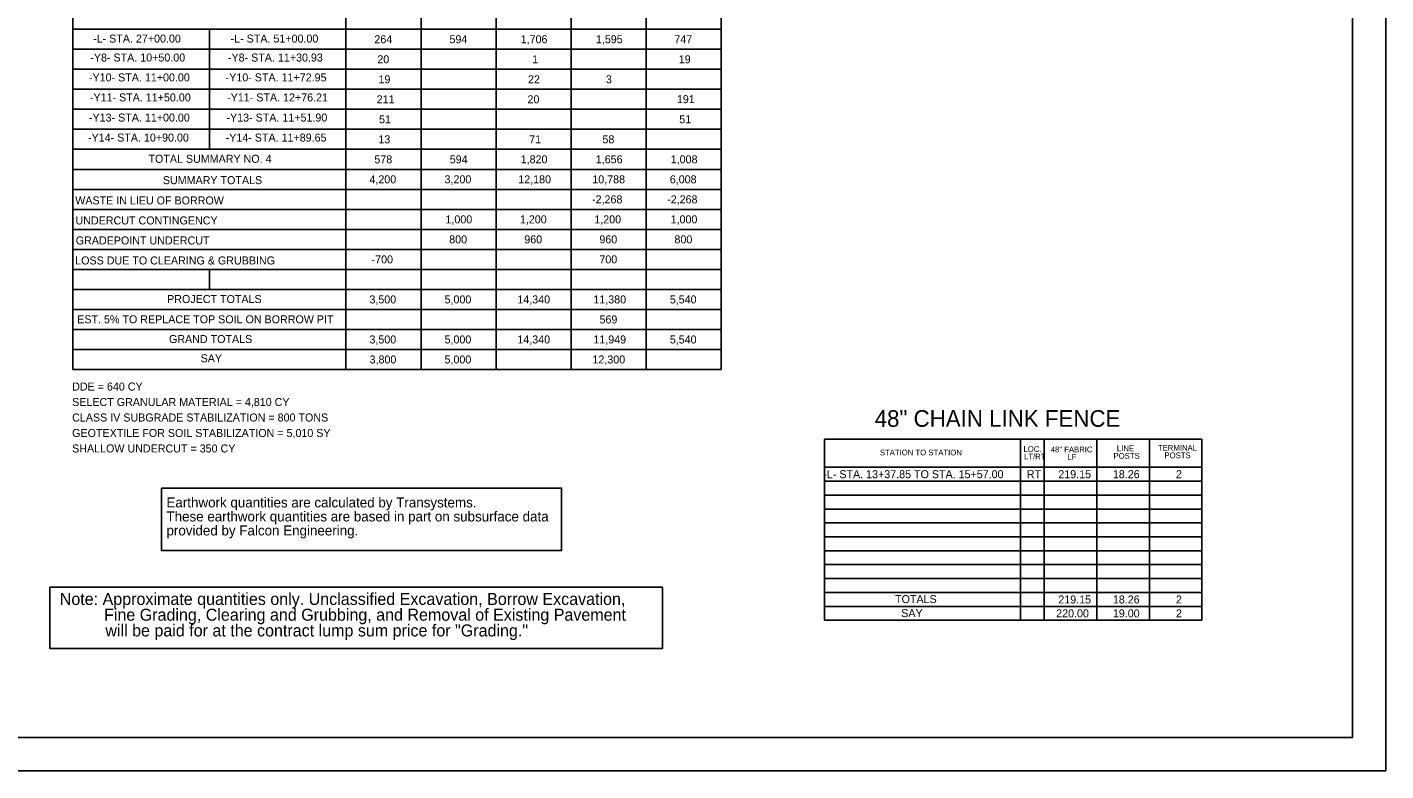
# Model space of a CAD drawing. Extents: x 573680 to 575380, y -53324 to -52224.
# Drawn here: x 574361 to 575380, y -53324 to -52767 of the extents above; entities that cross this region are included whole.
import ezdxf

# ---------------------------------------------------------------- set-up
doc = ezdxf.new("R2010")
doc.units = 0
for name, color, linetype in [('Old_Level_1', 7, 'Continuous'), ('Prop Dimension Text', 7, 'Continuous'), ('Prop Grid Mask', 7, 'Continuous'), ('Prop XSC Text', 7, 'Continuous'), ('Sheet Plan And Profile CELL', 7, 'Continuous'), ('Sheet Plot Border Outside CELL', 7, 'Continuous'), ('Sheet Summary Combination CELL', 7, 'Continuous'), ('Sheet Summary Combination Grid CELL', 7, 'Continuous'), ('Sheet Summary Earthwork CELL', 7, 'Continuous')]:
    doc.layers.add(name, color=color, linetype=linetype)

msp = doc.modelspace()

# ---------------------------------------------------------------- linework, layer by layer
at = {"layer": 'Prop Grid Mask'}
msp.add_lwpolyline([(574378.2, -53186.6), (574837.5, -53186.6), (574837.5, -53232.7), (574378.2, -53232.7)], close=True, dxfattribs=at)
at = {"layer": 'Sheet Plan And Profile CELL'}
msp.add_lwpolyline([(575354.9, -52249.3), (573854.9, -52249.3), (573854.9, -53299.3), (575354.9, -53299.3)], close=True, dxfattribs=at)
at = {"layer": 'Sheet Plot Border Outside CELL'}
msp.add_lwpolyline([(573679.9, -53324.3), (575379.9, -53324.3), (575379.9, -52224.3), (573679.9, -52224.3)], close=True, dxfattribs=at)
at = {"layer": 'Sheet Summary Combination CELL'}
for p, q in [((575084.8, -53075.9), (575084.8, -53075.9)), ((575090.1, -53076), (575090.1, -53076)), ((575097.7, -53075.8), (575097.7, -53075.8)), ((575102.4, -53075.9), (575102.4, -53075.9))]:
    msp.add_line(p, q, dxfattribs=at)
at = {"layer": 'Sheet Summary Combination Grid CELL'}
for p, q in [((574395.4, -52348.5), (574395.4, -53023.5)), ((574600.2, -52348.5), (574600.2, -53023.5)), ((574656.5, -52348.5), (574656.5, -53023.5)), ((574712.8, -52348.5), (574712.8, -53023.5)), ((574769.1, -52348.5), (574769.1, -53023.5)), ((574825.3, -52348.5), (574825.3, -53023.5)), ((574881.6, -52348.5), (574881.6, -53023.5)), ((574395.4, -52768.5), (574881.6, -52768.5)), ((574497.9, -52768.5), (574497.9, -52858.5)), ((574395.4, -52783.5), (574881.6, -52783.5)), ((574395.4, -52798.4), (574881.6, -52798.4)), ((574395.4, -52813.4), (574881.6, -52813.4)), ((574395.4, -52828.5), (574881.6, -52828.5)), ((574395.4, -52843.5), (574881.6, -52843.5)), ((574395.4, -52858.5), (574881.6, -52858.5)), ((574395.4, -52873.5), (574881.6, -52873.5)), ((574395.4, -52888.5), (574881.6, -52888.5)), ((574395.4, -52903.5), (574881.6, -52903.5)), ((574395.4, -52903.5), (574881.6, -52903.5)), ((574395.4, -52918.5), (574881.6, -52918.5)), ((574395.4, -52918.5), (574881.6, -52918.5)), ((574395.4, -52933.5), (574881.6, -52933.5)), ((574395.4, -52933.5), (574881.6, -52933.5)), ((574395.4, -52948.5), (574881.6, -52948.5)), ((574395.4, -52948.5), (574881.6, -52948.5)), ((574497.9, -52948.5), (574497.9, -52963.5)), ((574395.4, -52963.5), (574881.6, -52963.5)), ((574395.4, -52963.5), (574881.6, -52963.5)), ((574395.4, -52978.5), (574881.6, -52978.5)), ((574395.4, -52993.5), (574881.6, -52993.5)), ((574395.4, -53008.5), (574881.6, -53008.5)), ((574395.4, -53023.5), (574881.6, -53023.5)), ((574959, -53075.8), (575242, -53075.8)), ((574959, -53075.8), (574959, -53211.5)), ((575106, -53075.8), (575106, -53211.5)), ((575123.8, -53075.8), (575123.8, -53211.5)), ((575163.2, -53075.8), (575163.2, -53211.5)), ((575202.6, -53075.8), (575202.6, -53211.5)), ((575242, -53075.8), (575242, -53211.5)), ((574959, -53096.8), (575242, -53096.8)), ((574959, -53107.3), (575242, -53107.3)), ((574959, -53117.7), (575242, -53117.7)), ((574959, -53128.1), (575242, -53128.1)), ((574959, -53138.5), (575242, -53138.5)), ((574959, -53148.9), (575242, -53148.9)), ((574959, -53159.4), (575242, -53159.4)), ((574959, -53169.8), (575242, -53169.8)), ((574959, -53180.2), (575242, -53180.2)), ((574959, -53190.6), (575242, -53190.6)), ((574959, -53201.1), (575242, -53201.1)), ((574959, -53211.5), (575242, -53211.5))]:
    msp.add_line(p, q, dxfattribs=at)
at = {"layer": 'Sheet Summary Earthwork CELL'}
msp.add_lwpolyline([(574461.9, -53112.4), (574761.9, -53112.4), (574761.9, -53159.2), (574461.9, -53159.2)], close=True, dxfattribs=at)

# ---------------------------------------------------------------- texts
at = {"layer": 'Old_Level_1'}
for s, p in [('DDE = 640 CY', (574394.9, -53039.3)), ('SELECT GRANULAR MATERIAL = 4,810 CY', (574394.9, -53050.9)), ('CLASS IV SUBGRADE STABILIZATION = 800 TONS', (574394.9, -53062.5)), ('GEOTEXTILE FOR SOIL STABILIZATION = 5,010 SY', (574394.9, -53074.1)), ('SHALLOW UNDERCUT = 350 CY', (574394.9, -53085.7))]:
    msp.add_text(s, height=6, rotation=360, dxfattribs=at).set_placement(p)
at = {"layer": 'Prop Dimension Text'}
for s, p in [('-L- STA. 13+37.85 TO STA. 15+57.00', (574958.1, -53105)), ('RT', (575110.7, -53105)), ('219.15', (575134.3, -53105)), ('18.26', (575175.2, -53105)), ('2', (575222.5, -53105)), ('219.15', (575134.3, -53198.9)), ('18.26', (575175.2, -53198.9)), ('2', (575222.5, -53198.9)), ('220.00', (575132.7, -53209.3)), ('19.00', (575175.2, -53209.3)), ('2', (575222.5, -53209.3))]:
    msp.add_text(s, height=6, dxfattribs=at).set_placement(p)
for s, p in [('TOTALS', (575011.9, -53198.6)), ('SAY', (575016.5, -53209.1))]:
    msp.add_text(s, height=6, rotation=0, dxfattribs=at).set_placement(p)
at = {"layer": 'Prop XSC Text'}
for s, p in [('Note: Approximate quantities only. Unclassified Excavation, Borrow Excavation, ', (574385.6, -53200)), ('Fine Grading, Clearing and Grubbing, and Removal of Existing Pavement', (574418.8, -53211.8)), ('will be paid for at the contract lump sum price for "Grading."', (574419.8, -53223.6))]:
    msp.add_text(s, height=9, dxfattribs=at).set_placement(p)
at = {"layer": 'Sheet Summary Combination CELL'}
for s, height, p in [('-L- STA. 27+00.00', 6, (574410.6, -52778.5)), ('-L- STA. 51+00.00', 6, (574513.7, -52778.5)), ('264', 6, (574621.5, -52779)), ('594', 6, (574677.8, -52779)), ('1,706', 6, (574731.2, -52779)), ('1,595', 6, (574787.6, -52779)), ('747', 6, (574846.4, -52779)), ('-Y8- STA. 10+50.00', 6, (574408.5, -52792.7)), ('-Y8- STA. 11+30.93', 6, (574511.7, -52792.7)), ('20', 6, (574623.7, -52794)), ('1', 6, (574739.8, -52794)), ('19', 6, (574849.7, -52794)), ('-Y10- STA. 11+00.00', 6, (574407.5, -52807.6)), ('-Y10- STA. 11+72.95', 6, (574510, -52807.6)), ('19', 6, (574624.6, -52809)), ('22', 6, (574736.7, -52809)), ('3', 6, (574795.1, -52809)), ('-Y11- STA. 11+50.00', 6, (574408.2, -52822.6)), ('-Y11- STA. 12+76.21', 6, (574511.1, -52822.6)), ('211', 6, (574623.2, -52824)), ('20', 6, (574736.3, -52824)), ('191', 6, (574848.3, -52823.9)), ('-Y13- STA. 11+00.00', 6, (574407.5, -52837.7)), ('-Y13- STA. 11+51.90', 6, (574510.6, -52837.7)), ('51', 6, (574625, -52839)), ('51', 6, (574850.1, -52839)), ('-Y14- STA. 10+90.00', 6, (574406.8, -52852.7)), ('-Y14- STA. 11+89.65', 6, (574510, -52852.7)), ('13', 6, (574624.5, -52854)), ('71', 6, (574737.6, -52854)), ('58', 6, (574792.5, -52854)), ('TOTAL SUMMARY NO. 4', 6, (574452.1, -52868.6)), ('578', 6, (574621.5, -52869)), ('594', 6, (574678, -52869)), ('1,820', 6, (574731.2, -52869)), ('1,656', 6, (574787.5, -52869)), ('1,008', 6, (574843.7, -52869)), ('SUMMARY TOTALS', 6, (574462.9, -52884.6)), ('4,200', 6, (574617.8, -52884)), ('3,200', 6, (574674.1, -52884)), ('12,180', 6, (574729.4, -52884)), ('10,788', 6, (574784.9, -52884)), ('6,008', 6, (574843, -52884)), ('WASTE IN LIEU OF BORROW', 6, (574397.2, -52899.8)), ('-2,268', 6, (574784.7, -52899)), ('-2,268', 6, (574841, -52899)), ('UNDERCUT CONTINGENCY', 6, (574397.4, -52914.8)), ('1,000', 6, (574674.8, -52914)), ('1,200', 6, (574730.6, -52914)), ('1,200', 6, (574786.4, -52914)), ('1,000', 6, (574843.6, -52914)), ('GRADEPOINT UNDERCUT', 6, (574397.6, -52929.8)), ('800', 6, (574677.6, -52929)), ('960', 6, (574733.9, -52929)), ('960', 6, (574790.2, -52929)), ('800', 6, (574846.5, -52929)), ('LOSS DUE TO CLEARING & GRUBBING', 6, (574397.2, -52944.8)), ('-700', 6, (574619.4, -52944)), ('700', 6, (574790.2, -52944)), ('PROJECT TOTALS', 6, (574466.1, -52973.7)), ('3,500', 6, (574617.8, -52974)), ('5,000', 6, (574674.1, -52974)), ('14,340', 6, (574728.7, -52974)), ('11,380', 6, (574785.7, -52974)), ('5,540', 6, (574843, -52974)), ('EST. 5% TO REPLACE TOP SOIL ON BORROW PIT', 6, (574398.7, -52988.9)), ('569', 6, (574790.3, -52989)), ('GRAND TOTALS', 6, (574467.5, -53003.7)), ('3,500', 6, (574617.8, -53004)), ('5,000', 6, (574674.1, -53004)), ('14,340', 6, (574728.7, -53004)), ('11,949', 6, (574785.7, -53004)), ('5,540', 6, (574843, -53004)), ('SAY', 6, (574491.2, -53018.1)), ('3,800', 6, (574617.9, -53019)), ('5,000', 6, (574674.1, -53019)), ('12,300', 6, (574785, -53019)), ('STATION TO STATION', 4.332, (575000.5, -53087.9)), ('LOC.', 4.33, (575108.2, -53085.3)), ('48" FABRIC', 4.33, (575128.6, -53085.6)), ('LINE', 4.33, (575178.2, -53084.8)), ('TERMINAL', 4.33, (575209, -53084.4)), ('LT/RT', 4.33, (575108.6, -53090.9)), ('LF', 4.33, (575141, -53091.2)), ('POSTS', 4.33, (575175.7, -53090.4)), ('POSTS', 4.33, (575213.9, -53090))]:
    msp.add_text(s, height=height, dxfattribs=at).set_placement(p)
msp.add_text('48" CHAIN LINK FENCE', height=12.5, rotation=0.0119, dxfattribs=at).set_placement((574996.6, -53066.5))
at = {"layer": 'Sheet Summary Earthwork CELL'}
for s, p in [('Earthwork quantities are calculated by Transystems. ', (574465.6, -53126.9)), ('These earthwork quantities are based in part on subsurface data ', (574465.6, -53137.4)), ('provided by Falcon Engineering.', (574465.6, -53147.9))]:
    msp.add_text(s, height=7.5, dxfattribs=at).set_placement(p)

doc.saveas('drawing.dxf')
